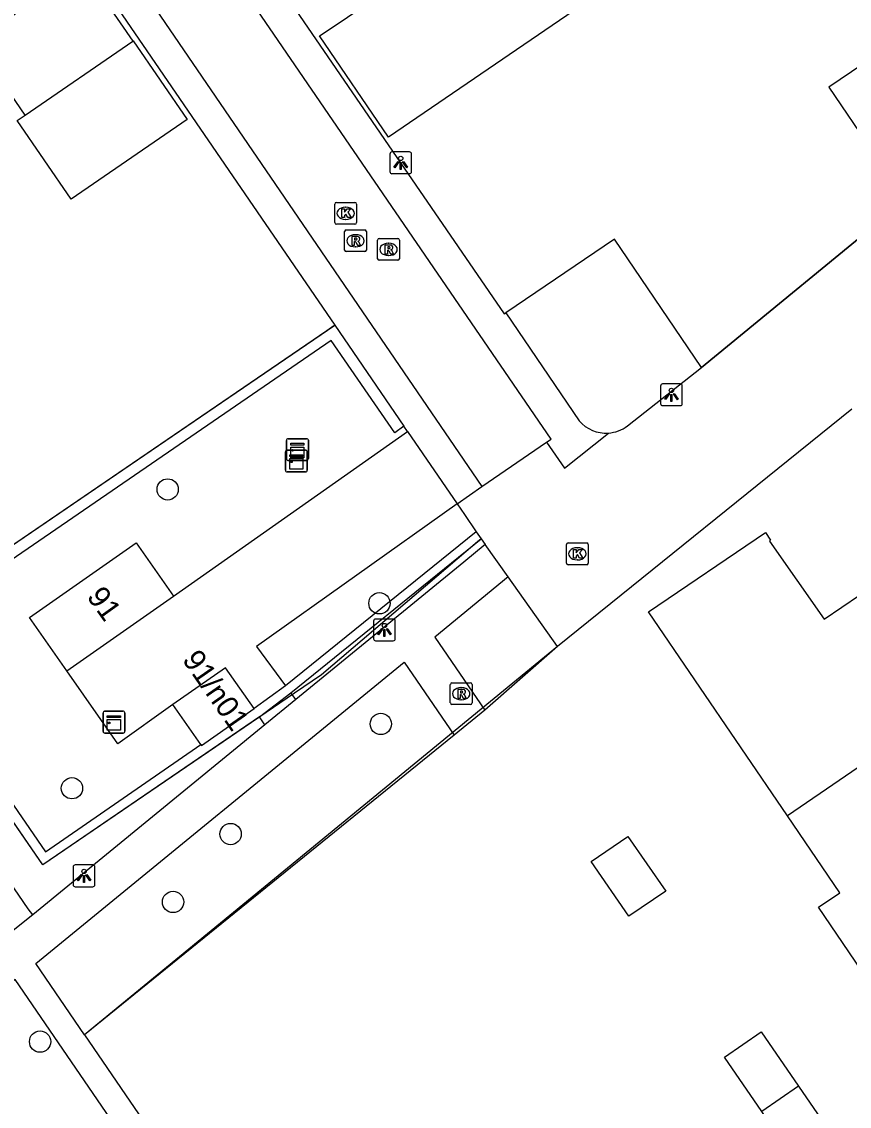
# Model space of a CAD drawing. Extents: x 155275 to 156263, y 382654 to 383635.
# Drawn here: x 155610.74 to 155648.73, y 383140.81 to 383190.6 of the extents above; entities that cross this region are included whole.
import ezdxf

# ---------------------------------------------------------------- set-up
doc = ezdxf.new("R2010")
doc.units = 0
for name, color, linetype in [('IMGEO_Boom', 7, 'Continuous'), ('IMGEO_Groenvoorziening', 7, 'Continuous'), ('IMGEO_Haag', 7, 'Continuous'), ('IMGEO_Hek', 7, 'Continuous'), ('IMGEO_Kast', 7, 'Continuous'), ('IMGEO_Kolk', 7, 'Continuous'), ('IMGEO_Lichtpunt', 7, 'Continuous'), ('IMGEO_Muur', 7, 'Continuous'), ('IMGEO_Pand', 7, 'Continuous'), ('IMGEO_Pand_nummerreeks', 7, 'Continuous'), ('IMGEO_Rijbaan_lokaal_open', 7, 'Continuous'), ('IMGEO_Rioolput', 7, 'Continuous'), ('IMGEO_Voetpad_open', 7, 'Continuous')]:
    doc.layers.add(name, color=color, linetype=linetype)

msp = doc.modelspace()

# ---------------------------------------------------------------- linework, layer by layer
at = {"layer": 'IMGEO_Boom'}
for centre in [(155617.44, 383169.125), (155627.162, 383163.901), (155627.224, 383158.361), (155613.048, 383155.409), (155620.327, 383153.305), (155617.688, 383150.19), (155611.585, 383143.777)]:
    msp.add_circle(centre, 0.489, dxfattribs=at)
at = {"layer": 'IMGEO_Groenvoorziening'}
for points in [[(155635.334, 383161.916), (155632.001, 383158.991)], [(155623.326, 383159.478), (155623.158, 383159.705), (155623.094, 383159.792)], [(155621.904, 383158.314), (155621.66, 383158.683)], [(155630.588, 383157.845), (155613.622, 383144.086)]]:
    msp.add_lwpolyline(points, dxfattribs=at)
at = {"layer": 'IMGEO_Haag'}
for points in [[(155604.389, 383162.527), (155625.107, 383176.674)], [(155628.287, 383172.031), (155627.871, 383171.732), (155624.938, 383175.959), (155605.072, 383162.322), (155611.84, 383152.49), (155618.959, 383157.415)], [(155631.606, 383167.187), (155622.856, 383160.114)], [(155623.094, 383159.792), (155631.833, 383166.856)], [(155621.66, 383158.683), (155611.707, 383151.893), (155604.389, 383162.527)], [(155621.66, 383158.683), (155623.094, 383159.792)]]:
    msp.add_lwpolyline(points, dxfattribs=at)
at = {"layer": 'IMGEO_Hek'}
for points in [[(155631.829, 383166.862), (155631.667, 383166.724), (155624.502, 383160.621), (155623.258, 383159.772), (155621.623, 383158.657), (155611.707, 383151.893), (155604.52, 383162.337), (155604.388, 383162.528), (155624.746, 383176.428), (155625.069, 383176.648)], [(155635.334, 383161.916), (155613.885, 383144.299), (155613.623, 383144.084)]]:
    msp.add_lwpolyline(points, dxfattribs=at)
at = {"layer": 'IMGEO_Kast'}
for p, q in [((155622.897, 383170.532), (155622.897, 383171.373)), ((155622.897, 383171.373), (155622.897, 383170.532)), ((155622.972, 383171.457), (155623.813, 383171.457)), ((155623.813, 383171.457), (155622.972, 383171.457)), ((155623.897, 383171.382), (155623.897, 383170.541)), ((155623.897, 383170.541), (155623.897, 383171.382)), ((155622.845, 383170.006), (155622.845, 383170.847)), ((155622.845, 383170.847), (155622.845, 383170.006)), ((155622.92, 383170.931), (155623.761, 383170.931)), ((155623.761, 383170.931), (155622.92, 383170.931)), ((155623.845, 383170.856), (155623.845, 383170.015)), ((155623.845, 383170.015), (155623.845, 383170.856)), ((155623.822, 383170.457), (155622.981, 383170.457)), ((155622.981, 383170.457), (155623.822, 383170.457)), ((155623.77, 383169.931), (155622.929, 383169.931)), ((155622.929, 383169.931), (155623.77, 383169.931)), ((155614.473, 383158.019), (155614.473, 383158.86)), ((155614.473, 383158.86), (155614.473, 383158.019)), ((155614.548, 383158.944), (155615.389, 383158.944)), ((155615.389, 383158.944), (155614.548, 383158.944)), ((155615.473, 383158.869), (155615.473, 383158.028)), ((155615.473, 383158.028), (155615.473, 383158.869)), ((155615.398, 383157.944), (155614.557, 383157.944)), ((155614.557, 383157.944), (155615.398, 383157.944))]:
    msp.add_line(p, q, dxfattribs=at)
for points in [[(155623.092, 383171.247), (155623.692, 383171.247), (155623.692, 383171.162), (155623.092, 383171.162), (155623.092, 383171.247)], [(155623.04, 383170.721), (155623.64, 383170.721), (155623.64, 383170.636), (155623.04, 383170.636), (155623.04, 383170.721)], [(155623.092, 383171.072), (155623.692, 383171.072), (155623.692, 383170.583), (155623.092, 383170.583), (155623.092, 383171.072)], [(155623.04, 383170.546), (155623.64, 383170.546), (155623.64, 383170.057), (155623.04, 383170.057), (155623.04, 383170.546)], [(155614.668, 383158.734), (155615.268, 383158.734), (155615.268, 383158.649), (155614.668, 383158.649), (155614.668, 383158.734)], [(155614.668, 383158.559), (155615.268, 383158.559), (155615.268, 383158.07), (155614.668, 383158.07), (155614.668, 383158.559)]]:
    msp.add_lwpolyline(points, dxfattribs=at)
for centre in [(155623.176, 383170.921), (155623.124, 383170.395), (155614.752, 383158.408)]:
    msp.add_circle(centre, 0.0377, dxfattribs=at)
for centre, start, end in [((155622.975, 383171.379), 92.4484, 184.2845), ((155622.975, 383171.379), 92.4484, 184.2845), ((155623.819, 383171.379), 2.4484, 94.2845), ((155623.819, 383171.379), 2.4484, 94.2845), ((155622.923, 383170.853), 92.4484, 184.2845), ((155622.923, 383170.853), 92.4484, 184.2845), ((155623.767, 383170.853), 2.4484, 94.2845), ((155623.767, 383170.853), 2.4484, 94.2845), ((155622.975, 383170.535), 182.4484, 274.2845), ((155622.975, 383170.535), 182.4484, 274.2845), ((155623.819, 383170.535), 272.4484, 4.2845), ((155623.819, 383170.535), 272.4484, 4.2845), ((155622.923, 383170.009), 182.4484, 274.2845), ((155622.923, 383170.009), 182.4484, 274.2845), ((155623.767, 383170.009), 272.4484, 4.2845), ((155623.767, 383170.009), 272.4484, 4.2845), ((155614.551, 383158.866), 92.4484, 184.2845), ((155614.551, 383158.866), 92.4484, 184.2845), ((155615.395, 383158.866), 2.4484, 94.2845), ((155615.395, 383158.866), 2.4484, 94.2845), ((155614.551, 383158.022), 182.4484, 274.2845), ((155614.551, 383158.022), 182.4484, 274.2845), ((155615.395, 383158.022), 272.4484, 4.2845), ((155615.395, 383158.022), 272.4484, 4.2845)]:
    msp.add_arc(centre, 0.0779, start, end, dxfattribs=at)
at = {"layer": 'IMGEO_Kolk'}
for p, q in [((155625.11, 383181.378), (155625.11, 383182.23)), ((155625.185, 383182.304), (155626.037, 383182.304)), ((155625.598, 383182.084), (155625.623, 383182.084)), ((155626.111, 383182.23), (155626.111, 383181.378)), ((155626.037, 383181.304), (155625.185, 383181.304)), ((155625.621, 383181.524), (155625.596, 383181.524)), ((155635.745, 383165.746), (155635.745, 383166.598)), ((155635.82, 383166.672), (155636.672, 383166.672)), ((155636.746, 383166.598), (155636.746, 383165.746)), ((155636.233, 383166.452), (155636.258, 383166.452)), ((155636.672, 383165.672), (155635.82, 383165.672)), ((155636.256, 383165.892), (155636.231, 383165.892))]:
    msp.add_line(p, q, dxfattribs=at)
for points in [[(155625.11, 383181.378), (155625.11, 383182.23)], [(155625.185, 383182.304), (155626.037, 383182.304)], [(155626.111, 383182.23), (155626.111, 383181.378)], [(155625.431, 383182.004), (155625.554, 383182.004), (155625.554, 383181.853), (155625.684, 383182.004), (155625.848, 383182.004), (155625.702, 383181.853), (155625.855, 383181.604), (155625.703, 383181.604), (155625.618, 383181.768), (155625.554, 383181.701), (155625.554, 383181.604), (155625.431, 383181.604), (155625.431, 383182.004)], [(155626.037, 383181.304), (155625.185, 383181.304)], [(155635.745, 383165.746), (155635.745, 383166.598)], [(155635.82, 383166.672), (155636.672, 383166.672)], [(155636.746, 383166.598), (155636.746, 383165.746)], [(155636.066, 383166.372), (155636.189, 383166.372), (155636.189, 383166.221), (155636.319, 383166.372), (155636.483, 383166.372), (155636.337, 383166.221), (155636.49, 383165.972), (155636.338, 383165.972), (155636.253, 383166.136), (155636.189, 383166.069), (155636.189, 383165.972), (155636.066, 383165.972), (155636.066, 383166.372)], [(155636.672, 383165.672), (155635.82, 383165.672)]]:
    msp.add_lwpolyline(points, dxfattribs=at)
for centre, start, end in [((155625.187, 383182.228), 91.552, 178.448), ((155625.187, 383182.228), 91.552, 178.448), ((155626.035, 383182.228), 1.552, 88.448), ((155626.035, 383182.228), 1.552, 88.448), ((155625.187, 383181.38), 181.552, 268.448), ((155625.187, 383181.38), 181.552, 268.448), ((155626.035, 383181.38), 271.552, 358.448), ((155626.035, 383181.38), 271.552, 358.448), ((155635.822, 383166.596), 91.552, 178.448), ((155635.822, 383166.596), 91.552, 178.448), ((155636.67, 383166.596), 1.552, 88.448), ((155636.67, 383166.596), 1.552, 88.448), ((155635.822, 383165.748), 181.552, 268.448), ((155635.822, 383165.748), 181.552, 268.448), ((155636.67, 383165.748), 271.552, 358.448), ((155636.67, 383165.748), 271.552, 358.448)]:
    msp.add_arc(centre, 0.0765, start, end, dxfattribs=at)
for centre, major_axis, ratio, start_param, end_param in [((155625.597, 383181.804), (-0.387, 0.002), 0.722429, 4.712389, 7.853982), ((155625.622, 383181.804), (-0.39, 0.002), 0.717154, 1.570796, 4.712389), ((155636.232, 383166.172), (-0.387, 0.002), 0.722429, 4.712389, 7.853982), ((155636.257, 383166.172), (-0.39, 0.002), 0.717154, 1.570796, 4.712389)]:
    msp.add_ellipse(centre, major_axis=major_axis, ratio=ratio, start_param=start_param, end_param=end_param, dxfattribs=at)
at = {"layer": 'IMGEO_Lichtpunt'}
for p, q in [((155627.639, 383184.525), (155627.639, 383183.718)), ((155627.639, 383184.525), (155627.639, 383183.718)), ((155628.541, 383184.62), (155627.733, 383184.62)), ((155628.541, 383184.62), (155627.733, 383184.62)), ((155628.635, 383183.718), (155628.635, 383184.525)), ((155628.635, 383183.718), (155628.635, 383184.525)), ((155627.733, 383183.624), (155628.541, 383183.624)), ((155627.733, 383183.624), (155628.541, 383183.624)), ((155640.065, 383173.874), (155640.065, 383173.067)), ((155640.065, 383173.874), (155640.065, 383173.067)), ((155640.967, 383173.969), (155640.159, 383173.969)), ((155640.967, 383173.969), (155640.159, 383173.969)), ((155641.061, 383173.067), (155641.061, 383173.874)), ((155641.061, 383173.067), (155641.061, 383173.874)), ((155640.159, 383172.973), (155640.967, 383172.973)), ((155640.159, 383172.973), (155640.967, 383172.973)), ((155627.793, 383163.176), (155626.985, 383163.176)), ((155627.793, 383163.176), (155626.985, 383163.176)), ((155626.891, 383163.081), (155626.891, 383162.274)), ((155626.891, 383163.081), (155626.891, 383162.274)), ((155627.887, 383162.274), (155627.887, 383163.081)), ((155627.887, 383162.274), (155627.887, 383163.081)), ((155626.985, 383162.18), (155627.793, 383162.18)), ((155626.985, 383162.18), (155627.793, 383162.18)), ((155613.103, 383151.79), (155613.103, 383150.983)), ((155613.103, 383151.79), (155613.103, 383150.983)), ((155614.005, 383151.885), (155613.197, 383151.885)), ((155614.005, 383151.885), (155613.197, 383151.885)), ((155614.099, 383150.983), (155614.099, 383151.79)), ((155614.099, 383150.983), (155614.099, 383151.79)), ((155613.197, 383150.889), (155614.005, 383150.889)), ((155613.197, 383150.889), (155614.005, 383150.889))]:
    msp.add_line(p, q, dxfattribs=at)
for points in [[(155628.013, 383184.189), (155628.052, 383184.161), (155627.864, 383183.899), (155627.826, 383183.926), (155628.013, 383184.189)], [(155628.115, 383184.141), (155628.162, 383184.141), (155628.162, 383183.819), (155628.115, 383183.819), (155628.115, 383184.141)], [(155628.225, 383184.161), (155628.263, 383184.188), (155628.45, 383183.926), (155628.411, 383183.898), (155628.225, 383184.161)], [(155640.439, 383173.538), (155640.478, 383173.51), (155640.29, 383173.248), (155640.252, 383173.275), (155640.439, 383173.538)], [(155640.541, 383173.49), (155640.588, 383173.49), (155640.588, 383173.168), (155640.541, 383173.168), (155640.541, 383173.49)], [(155640.651, 383173.51), (155640.689, 383173.537), (155640.876, 383173.275), (155640.837, 383173.247), (155640.651, 383173.51)], [(155627.265, 383162.745), (155627.304, 383162.717), (155627.116, 383162.455), (155627.078, 383162.482), (155627.265, 383162.745)], [(155627.367, 383162.697), (155627.414, 383162.697), (155627.414, 383162.375), (155627.367, 383162.375), (155627.367, 383162.697)], [(155627.477, 383162.717), (155627.515, 383162.744), (155627.702, 383162.482), (155627.663, 383162.454), (155627.477, 383162.717)], [(155613.477, 383151.454), (155613.516, 383151.426), (155613.328, 383151.164), (155613.29, 383151.191), (155613.477, 383151.454)], [(155613.579, 383151.406), (155613.626, 383151.406), (155613.626, 383151.084), (155613.579, 383151.084), (155613.579, 383151.406)], [(155613.689, 383151.426), (155613.727, 383151.453), (155613.914, 383151.191), (155613.875, 383151.163), (155613.689, 383151.426)]]:
    msp.add_lwpolyline(points, dxfattribs=at)
for centre in [(155628.138, 383184.323), (155640.564, 383173.672), (155627.39, 383162.879), (155613.602, 383151.588)]:
    msp.add_circle(centre, 0.0994, dxfattribs=at)
for centre, start, end in [((155627.733, 383184.525), 90, 180), ((155627.733, 383184.525), 90, 180), ((155628.541, 383184.525), 0, 90), ((155628.541, 383184.525), 0, 90), ((155627.733, 383183.718), 180, 270), ((155627.733, 383183.718), 180, 270), ((155628.541, 383183.718), 270, 0), ((155628.541, 383183.718), 270, 360), ((155640.159, 383173.874), 90, 180), ((155640.159, 383173.874), 90, 180), ((155640.967, 383173.874), 0, 90), ((155640.967, 383173.874), 0, 90), ((155640.159, 383173.067), 180, 270), ((155640.159, 383173.067), 180, 270), ((155640.967, 383173.067), 270, 0), ((155640.967, 383173.067), 270, 360), ((155626.985, 383163.081), 90, 180), ((155626.985, 383163.081), 90, 180), ((155627.793, 383163.081), 0, 90), ((155627.793, 383163.081), 0, 90), ((155626.985, 383162.274), 180, 270), ((155626.985, 383162.274), 180, 270), ((155627.793, 383162.274), 270, 0), ((155627.793, 383162.274), 270, 360), ((155613.197, 383151.79), 90, 180), ((155613.197, 383151.79), 90, 180), ((155614.005, 383151.79), 0, 90), ((155614.005, 383151.79), 0, 90), ((155613.197, 383150.983), 180, 270), ((155613.197, 383150.983), 180, 270), ((155614.005, 383150.983), 270, 0), ((155614.005, 383150.983), 270, 360)]:
    msp.add_arc(centre, 0.0946, start, end, dxfattribs=at)
at = {"layer": 'IMGEO_Muur'}
msp.add_lwpolyline([(155651.272, 383182.377), (155651.229, 383182.342), (155641.945, 383174.729)], dxfattribs=at)
at = {"layer": 'IMGEO_Pand'}
for points in [[(155650.839, 383212.255), (155654.9, 383206.346), (155651.66, 383204.069), (155651.234, 383203.771), (155652.097, 383202.543), (155652.522, 383202.842), (155652.762, 383202.5), (155627.57, 383185.305), (155624.415, 383189.945), (155625.261, 383190.513), (155630.206, 383193.892), (155634.389, 383196.757), (155634.819, 383196.13), (155640.175, 383199.802), (155640.467, 383199.372), (155643.571, 383201.501), (155642.786, 383202.617), (155643.191, 383202.9), (155641.554, 383205.325), (155643.277, 383206.53), (155643.083, 383206.807), (155650.839, 383212.255)], [(155659.44, 383189.029), (155657.359, 383192.071), (155659.082, 383193.248), (155659.46, 383192.694), (155662.684, 383194.892), (155657.792, 383202.114), (155649.406, 383196.433), (155649.737, 383195.945), (155649.869, 383196.034), (155653.046, 383191.345), (155652.458, 383190.947), (155652.548, 383190.814), (155649.873, 383189.002), (155647.793, 383187.593), (155649.758, 383184.692), (155649.626, 383184.602), (155651.229, 383182.342)], [(155610.896, 383186.311), (155608.57, 383189.699), (155613.515, 383193.095), (155615.842, 383189.707)], [(155615.842, 383189.707), (155615.858, 383189.718), (155618.338, 383186.106), (155613.01, 383182.447), (155610.537, 383186.064), (155610.896, 383186.311)], [(155610.896, 383186.311), (155615.842, 383189.707)], [(155641.945, 383174.729), (155637.947, 383180.613), (155632.967, 383177.231)], [(155632.967, 383177.231), (155636.331, 383172.279)], [(155638.542, 383172.041), (155641.945, 383174.729)], [(155645.889, 383154.138), (155639.507, 383163.506), (155644.873, 383167.147), (155645.114, 383166.792), (155645.06, 383166.755), (155647.568, 383163.164), (155651.631, 383165.922), (155653.603, 383163.048), (155655.298, 383160.578), (155651.22, 383157.787)], [(155612.814, 383160.802), (155611.101, 383163.245), (155615.989, 383166.673), (155617.702, 383164.23)], [(155612.814, 383160.802), (155617.702, 383164.23)], [(155621.409, 383159.063), (155620.098, 383160.943), (155617.677, 383159.258)], [(155618.959, 383157.415), (155617.677, 383159.258)], [(155618.959, 383157.415), (155618.987, 383157.375), (155621.409, 383159.063)], [(155651.22, 383157.787), (155645.889, 383154.138)], [(155649.956, 383143.939), (155649.697, 383144.314), (155650.679, 383144.995), (155647.318, 383149.942), (155648.295, 383150.607), (155645.889, 383154.138)], [(155638.611, 383149.535), (155636.878, 383152.038), (155638.565, 383153.2), (155640.299, 383150.684), (155638.611, 383149.535)], [(155644.705, 383140.563), (155643, 383143.056), (155644.685, 383144.22), (155646.398, 383141.725)], [(155646.398, 383141.725), (155648.111, 383139.229), (155646.416, 383138.061), (155644.705, 383140.563)], [(155646.398, 383141.725), (155644.705, 383140.563)]]:
    msp.add_lwpolyline(points, dxfattribs=at)
for centre, radius, start, end in [((155637.561, 383173.331), 1.619, 220.5395, 273.7893), ((155637.567, 383173.327), 1.614, 273.6044, 307.1913)]:
    msp.add_arc(centre, radius, start, end, dxfattribs=at)
at = {"layer": 'IMGEO_Rijbaan_lokaal_open'}
for points in [[(155634.823, 383171.29), (155635.04, 383171.44), (155592.812, 383233.101)], [(155589.707, 383230.961), (155631.867, 383169.258)], [(155641.945, 383174.729), (155651.229, 383182.342)], [(155648.848, 383172.815), (155635.334, 383161.916)], [(155634.823, 383171.29), (155635.652, 383170.105), (155637.668, 383171.716)], [(155631.867, 383169.258), (155634.823, 383171.29)], [(155630.734, 383168.461), (155631.867, 383169.258)], [(155630.734, 383168.461), (155631.067, 383167.974), (155631.606, 383167.187)], [(155631.606, 383167.187), (155631.833, 383166.856)], [(155631.833, 383166.856), (155632.007, 383166.602)], [(155633.075, 383165.119), (155632.007, 383166.602)], [(155635.334, 383161.916), (155633.075, 383165.119)]]:
    msp.add_lwpolyline(points, dxfattribs=at)
at = {"layer": 'IMGEO_Rioolput'}
for p, q in [((155625.637, 383181.043), (155626.489, 383181.043)), ((155625.562, 383180.117), (155625.562, 383180.969)), ((155626.05, 383180.823), (155626.075, 383180.823)), ((155626.563, 383180.969), (155626.563, 383180.117)), ((155627.078, 383179.721), (155627.078, 383180.573)), ((155627.153, 383180.647), (155628.005, 383180.647)), ((155628.079, 383180.573), (155628.079, 383179.721)), ((155626.489, 383180.043), (155625.637, 383180.043)), ((155626.073, 383180.263), (155626.048, 383180.263)), ((155627.566, 383180.427), (155627.591, 383180.427)), ((155628.005, 383179.647), (155627.153, 383179.647)), ((155627.589, 383179.867), (155627.564, 383179.867)), ((155630.414, 383159.323), (155630.414, 383160.175)), ((155630.489, 383160.249), (155631.341, 383160.249)), ((155631.415, 383160.175), (155631.415, 383159.323)), ((155630.902, 383160.029), (155630.927, 383160.029)), ((155631.341, 383159.249), (155630.489, 383159.249)), ((155630.925, 383159.469), (155630.9, 383159.469))]:
    msp.add_line(p, q, dxfattribs=at)
for points in [[(155625.637, 383181.043), (155626.489, 383181.043)], [(155625.562, 383180.117), (155625.562, 383180.969)], [(155626.151, 383180.741), (155625.899, 383180.743), (155625.899, 383180.343)], [(155626.077, 383180.662), (155626.023, 383180.662), (155626.023, 383180.581)], [(155626.023, 383180.581), (155626.075, 383180.581)], [(155626.563, 383180.969), (155626.563, 383180.117)], [(155627.078, 383179.721), (155627.078, 383180.573)], [(155627.153, 383180.647), (155628.005, 383180.647)], [(155628.079, 383180.573), (155628.079, 383179.721)], [(155626.489, 383180.043), (155625.637, 383180.043)], [(155625.899, 383180.343), (155626.023, 383180.343), (155626.023, 383180.505), (155626.034, 383180.505)], [(155626.081, 383180.476), (155626.152, 383180.343), (155626.292, 383180.343), (155626.227, 383180.469)], [(155627.667, 383180.345), (155627.415, 383180.347), (155627.415, 383179.947)], [(155627.415, 383179.947), (155627.539, 383179.947), (155627.539, 383180.109), (155627.55, 383180.109)], [(155627.593, 383180.266), (155627.539, 383180.266), (155627.539, 383180.185)], [(155627.539, 383180.185), (155627.591, 383180.185)], [(155627.597, 383180.08), (155627.668, 383179.947), (155627.808, 383179.947), (155627.743, 383180.073)], [(155628.005, 383179.647), (155627.153, 383179.647)], [(155630.414, 383159.323), (155630.414, 383160.175)], [(155630.489, 383160.249), (155631.341, 383160.249)], [(155631.415, 383160.175), (155631.415, 383159.323)], [(155631.003, 383159.947), (155630.751, 383159.949), (155630.751, 383159.549)], [(155630.751, 383159.549), (155630.875, 383159.549), (155630.875, 383159.711), (155630.886, 383159.711)], [(155630.929, 383159.868), (155630.875, 383159.868), (155630.875, 383159.787)], [(155630.875, 383159.787), (155630.927, 383159.787)], [(155630.933, 383159.682), (155631.004, 383159.549), (155631.144, 383159.549), (155631.079, 383159.675)], [(155631.341, 383159.249), (155630.489, 383159.249)]]:
    msp.add_lwpolyline(points, dxfattribs=at)
for centre, radius, start, end in [((155625.639, 383180.967), 0.0765, 91.552, 178.448), ((155625.639, 383180.967), 0.0765, 91.552, 178.448), ((155626.487, 383180.967), 0.0765, 1.552, 88.448), ((155626.487, 383180.967), 0.0765, 1.552, 88.448), ((155626.059, 383180.77), 0.19, 274.7715, 282.9687), ((155626.083, 383180.566), 0.0964, 77.0061, 93.1865), ((155626.097, 383180.623), 0.0378, 276.6634, 79.6772), ((155626.15, 383180.631), 0.109, 350.3612, 89.416), ((155626.148, 383180.631), 0.112, 277.5842, 350.9817), ((155627.155, 383180.571), 0.0765, 91.552, 178.448), ((155627.155, 383180.571), 0.0765, 91.552, 178.448), ((155628.003, 383180.571), 0.0765, 1.552, 88.448), ((155628.003, 383180.571), 0.0765, 1.552, 88.448), ((155625.639, 383180.119), 0.0765, 181.552, 268.448), ((155625.639, 383180.119), 0.0765, 181.552, 268.448), ((155626.033, 383180.452), 0.0533, 26.0293, 88.6989), ((155626.132, 383180.416), 0.108, 29.5134, 73.7905), ((155626.487, 383180.119), 0.0765, 271.552, 358.448), ((155626.487, 383180.119), 0.0765, 271.552, 358.448), ((155627.549, 383180.056), 0.0533, 26.0293, 88.6989), ((155627.575, 383180.374), 0.19, 274.7715, 282.9687), ((155627.599, 383180.17), 0.0964, 77.0061, 93.1865), ((155627.613, 383180.227), 0.0378, 276.6634, 79.6772), ((155627.666, 383180.235), 0.109, 350.3612, 89.416), ((155627.664, 383180.235), 0.112, 277.5842, 350.9817), ((155627.648, 383180.02), 0.108, 29.5134, 73.7905), ((155627.155, 383179.723), 0.0765, 181.552, 268.448), ((155627.155, 383179.723), 0.0765, 181.552, 268.448), ((155628.003, 383179.723), 0.0765, 271.552, 358.448), ((155628.003, 383179.723), 0.0765, 271.552, 358.448), ((155630.491, 383160.173), 0.0765, 91.552, 178.448), ((155630.491, 383160.173), 0.0765, 91.552, 178.448), ((155631.339, 383160.173), 0.0765, 1.552, 88.448), ((155631.339, 383160.173), 0.0765, 1.552, 88.448), ((155630.885, 383159.658), 0.0533, 26.0293, 88.6989), ((155630.911, 383159.976), 0.19, 274.7715, 282.9687), ((155630.935, 383159.772), 0.0964, 77.0061, 93.1865), ((155630.949, 383159.829), 0.0378, 276.6634, 79.6772), ((155631.002, 383159.837), 0.109, 350.3612, 89.416), ((155631, 383159.837), 0.112, 277.5842, 350.9817), ((155630.984, 383159.622), 0.108, 29.5134, 73.7905), ((155630.491, 383159.325), 0.0765, 181.552, 268.448), ((155630.491, 383159.325), 0.0765, 181.552, 268.448), ((155631.339, 383159.325), 0.0765, 271.552, 358.448), ((155631.339, 383159.325), 0.0765, 271.552, 358.448)]:
    msp.add_arc(centre, radius, start, end, dxfattribs=at)
for centre, major_axis, ratio, start_param, end_param in [((155626.049, 383180.543), (-0.387, 0.002), 0.722429, 4.712389, 7.853982), ((155626.074, 383180.543), (-0.39, 0.002), 0.717154, 1.570796, 4.712389), ((155627.565, 383180.147), (-0.387, 0.002), 0.722429, 4.712389, 7.853982), ((155627.59, 383180.147), (-0.39, 0.002), 0.717154, 1.570796, 4.712389), ((155630.901, 383159.749), (-0.387, 0.002), 0.722429, 4.712389, 7.853982), ((155630.926, 383159.749), (-0.39, 0.002), 0.717154, 1.570796, 4.712389)]:
    msp.add_ellipse(centre, major_axis=major_axis, ratio=ratio, start_param=start_param, end_param=end_param, dxfattribs=at)
at = {"layer": 'IMGEO_Voetpad_open'}
for points in [[(155594.627, 383232.993), (155628.132, 383184.122), (155632.891, 383177.182), (155632.967, 383177.231)], [(155589.111, 383229.212), (155625.107, 383176.674)], [(155625.107, 383176.674), (155628.287, 383172.031)], [(155617.702, 383164.23), (155628.453, 383171.789)], [(155628.453, 383171.789), (155628.287, 383172.031)], [(155628.453, 383171.789), (155630.734, 383168.461)], [(155630.734, 383168.461), (155621.518, 383161.922), (155622.856, 383160.114)], [(155632.007, 383166.602), (155631.041, 383165.794), (155623.326, 383159.478)], [(155633.075, 383165.119), (155629.709, 383162.347), (155632.001, 383158.991)], [(155611.256, 383149.591), (155611.034, 383149.871), (155603.025, 383161.596)], [(155613.622, 383144.086), (155611.386, 383147.359), (155628.302, 383161.197), (155630.588, 383157.845)], [(155617.677, 383159.258), (155615.157, 383157.441), (155612.814, 383160.802)], [(155622.856, 383160.114), (155621.409, 383159.063)], [(155623.326, 383159.478), (155621.904, 383158.314)], [(155632.001, 383158.991), (155630.588, 383157.845)], [(155621.904, 383158.314), (155611.256, 383149.591)], [(155611.256, 383149.591), (155610.043, 383148.625)], [(155610.441, 383146.625), (155604.19, 383141.494), (155614.913, 383125.805), (155621.572, 383130.348), (155610.441, 383146.625)], [(155613.622, 383144.086), (155622.569, 383130.992)]]:
    msp.add_lwpolyline(points, dxfattribs=at)

# ---------------------------------------------------------------- texts
at = {"layer": 'IMGEO_Pand_nummerreeks'}
for s, rotation, p in [('91', 305.6491, (155613.696, 383164.203)), ('91/n01', 304.8242, (155618.079, 383161.307))]:
    msp.add_text(s, height=1, rotation=rotation, dxfattribs=at).set_placement(p)

doc.saveas('drawing.dxf')
